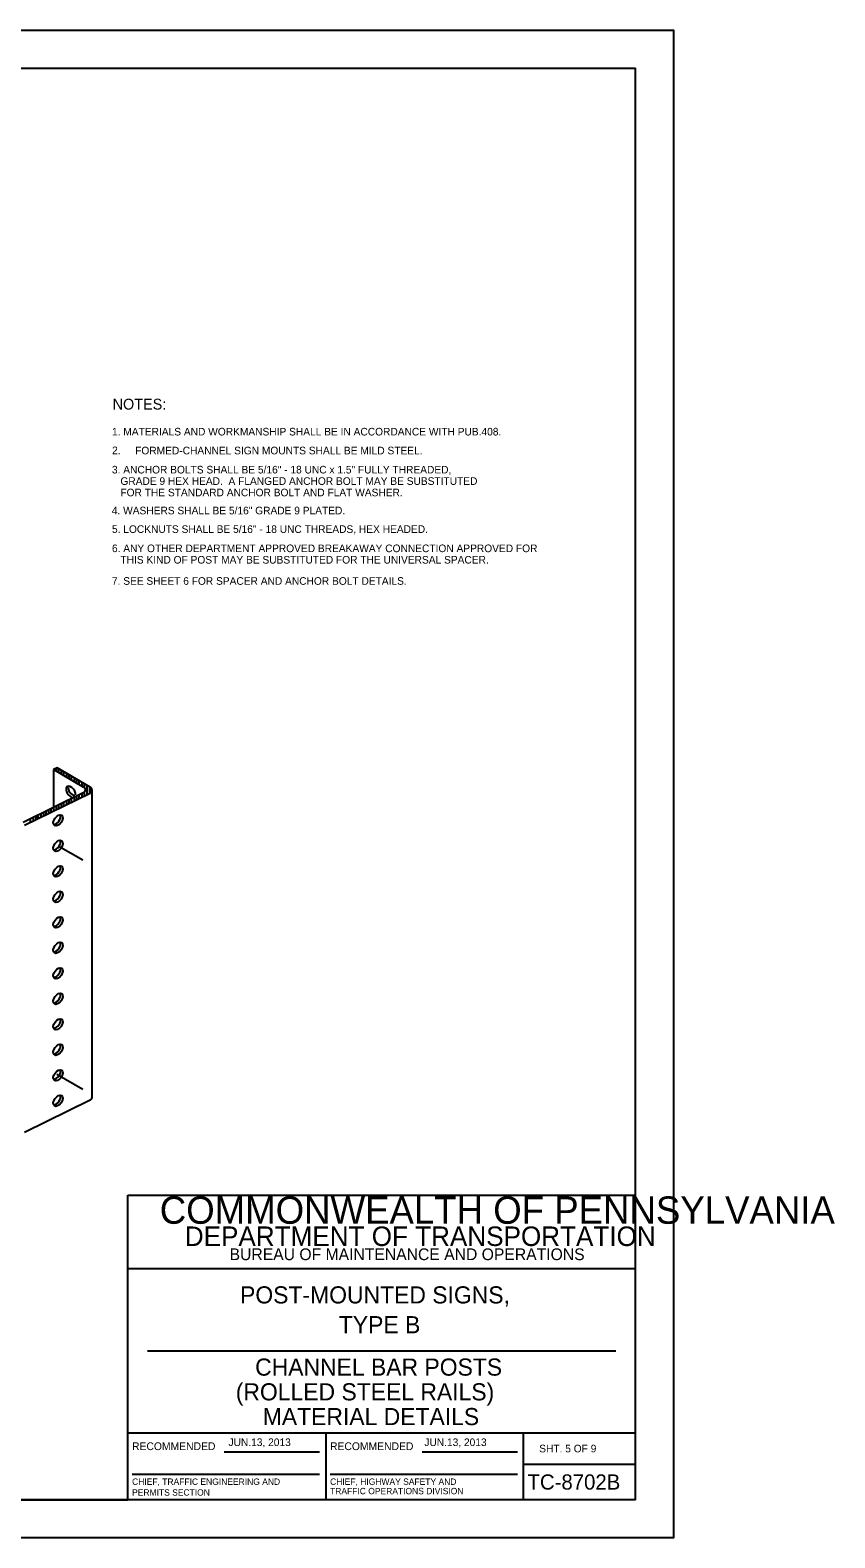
# Model space of a CAD drawing. Extents: x 644358 to 648627, y 294594 to 295782.
# Drawn here: x 648310 to 648627, y 295188 to 295782 of the extents above; entities that cross this region are included whole.
import ezdxf

# ---------------------------------------------------------------- set-up
doc = ezdxf.new("R2010")
doc.units = 0
for name, color, linetype in [('1', 7, 'Continuous'), ('2', 7, 'Continuous'), ('4', 7, 'Continuous'), ('PLT-BNDY', 7, 'Continuous')]:
    doc.layers.add(name, color=color, linetype=linetype)

msp = doc.modelspace()

# ---------------------------------------------------------------- linework, layer by layer
at = {"layer": '1'}
for p, q in [((647762.31, 295766.63), (648548.31, 295766.63)), ((648548.31, 295202.63), (648548.31, 295766.63)), ((648348.31, 295202.63), (648348.31, 295322.63)), ((648348.31, 295322.63), (648548.31, 295322.63)), ((648548.31, 295293.63), (648348.31, 295293.63)), ((648356.06, 295261.31), (648540.56, 295261.31)), ((648348.31, 295229), (648548.31, 295229)), ((648426.31, 295229), (648426.31, 295202.63)), ((648504.19, 295202.63), (648504.19, 295229)), ((648386.24, 295221.57), (648423.87, 295221.57)), ((648464.24, 295221.57), (648501.87, 295221.57)), ((648349.99, 295212.68), (648423.87, 295212.68)), ((648427.99, 295212.68), (648501.87, 295212.68)), ((648504.19, 295216.63), (648548.31, 295216.63)), ((648548.31, 295202.63), (647762.31, 295202.63)), ((647762.31, 295202.63), (648348.31, 295202.63))]:
    msp.add_line(p, q, dxfattribs=at)
at = {"layer": '2'}
for p, q in [((648320.53, 295491.03), (648319.03, 295490.28)), ((648331.03, 295483.28), (648319.03, 295490.28)), ((648319.03, 295490.28), (648319.03, 295475.53)), ((648320.03, 295490.78), (648320.03, 295489.78)), ((648333.53, 295483.4), (648320.53, 295491.03)), ((648321.03, 295490.65), (648321.03, 295489.03)), ((648322.03, 295490.03), (648322.03, 295488.4)), ((648323.03, 295489.53), (648323.03, 295487.9)), ((648324.15, 295488.9), (648324.15, 295487.28)), ((648325.03, 295488.4), (648325.03, 295486.78)), ((648326.03, 295487.78), (648326.03, 295486.15)), ((648327.15, 295487.15), (648327.15, 295485.53)), ((648328.15, 295486.53), (648328.15, 295485.03)), ((648329.03, 295485.9), (648329.03, 295484.4)), ((648330.15, 295485.4), (648330.15, 295483.9)), ((648307.03, 295469.65), (648331.03, 295481.4)), ((648307.65, 295468.4), (648333.53, 295481.03)), ((648327.15, 295479.4), (648327.15, 295477.9)), ((648327.4, 295479.53), (648327.4, 295479.53)), ((648328.15, 295479.9), (648328.15, 295478.4)), ((648329.03, 295480.53), (648329.03, 295479.03)), ((648330.15, 295480.9), (648330.15, 295479.4)), ((648331.15, 295484.78), (648331.15, 295483.15)), ((648331.15, 295481.53), (648331.15, 295479.9)), ((648332.15, 295484.15), (648332.15, 295480.4)), ((648333.15, 295483.65), (648333.15, 295480.9)), ((648334.15, 295482.4), (648334.15, 295360.9)), ((648315.03, 295473.53), (648315.03, 295472.03)), ((648316.03, 295474.03), (648316.03, 295472.53)), ((648317.03, 295474.53), (648317.03, 295473.03)), ((648318.03, 295474.9), (648318.03, 295473.53)), ((648319.03, 295475.53), (648319.03, 295474.03)), ((648320.03, 295476.03), (648320.03, 295474.53)), ((648321.03, 295476.4), (648321.03, 295474.9)), ((648322.03, 295477.03), (648322.03, 295475.53)), ((648323.03, 295477.53), (648323.03, 295476.03)), ((648324.15, 295477.9), (648324.15, 295476.4)), ((648325.03, 295478.4), (648325.03, 295476.9)), ((648326.03, 295479.03), (648326.03, 295477.53)), ((648309.9, 295471.03), (648309.9, 295469.53)), ((648311.03, 295471.53), (648311.03, 295470.15)), ((648312.03, 295472.03), (648312.03, 295470.53)), ((648312.9, 295472.53), (648312.9, 295471.03)), ((648314.03, 295473.03), (648314.03, 295471.53)), ((648319.4, 295468.28), (648319.4, 295468.28)), ((648319.4, 295458.28), (648319.4, 295458.28)), ((648330.53, 295454.65), (648320.9, 295460.15)), ((648319.4, 295448.15), (648319.4, 295448.15)), ((648319.4, 295438.15), (648319.4, 295438.15)), ((648319.4, 295428.15), (648319.4, 295428.15)), ((648319.4, 295418.03), (648319.4, 295418.03)), ((648319.4, 295408.03), (648319.4, 295408.03)), ((648319.4, 295398.03), (648319.4, 295398.03)), ((648319.4, 295387.9), (648319.4, 295387.9)), ((648319.4, 295377.9), (648319.4, 295377.9)), ((648319.4, 295367.9), (648319.4, 295367.9)), ((648330.53, 295364.28), (648320.28, 295370.15)), ((648307.65, 295347.4), (648333.53, 295360.15)), ((648319.4, 295357.9), (648319.4, 295357.9))]:
    msp.add_line(p, q, dxfattribs=at)
for centre, radius, start, end in [((648330.54, 295482.35), 1.08, 296.09542, 59.8656), ((648332.82, 295482.27), 1.35, 296.10629, 59.84607), ((648332.82, 295361.31), 1.35, 296.10629, 351.60882)]:
    msp.add_arc(centre, radius, start, end, dxfattribs=at)
for centre, major_axis, start_param, end_param in [((648325.85, 295481.54), (1.46, -2.03), 3.471768, 5.580344), ((648325.85, 295481.54), (1.46, -2.03), 0.572065, 3.471768), ((648326.72, 295482.16), (1.46, -2.03), 3.600978, 5.74606), ((648319.96, 295470.92), (-1.46, -2.03), 0.439655, 2.682207), ((648319.96, 295460.88), (-1.46, -2.03), 0.439655, 2.682207), ((648319.96, 295450.84), (-1.46, -2.03), 0.439655, 2.682207), ((648319.96, 295440.8), (-1.46, -2.03), 0.439655, 2.682207), ((648319.96, 295430.75), (-1.46, -2.03), 0.439655, 2.682207), ((648319.96, 295420.71), (-1.46, -2.03), 0.439655, 2.682207), ((648319.96, 295410.67), (-1.46, -2.03), 0.439655, 2.682207), ((648319.96, 295400.62), (-1.46, -2.03), 0.439655, 2.682207), ((648319.96, 295390.58), (-1.46, -2.03), 0.439655, 2.682207), ((648319.96, 295380.54), (-1.46, -2.03), 0.439655, 2.682207), ((648319.96, 295370.5), (-1.46, -2.03), 0.439655, 2.682207), ((648319.96, 295360.45), (-1.46, -2.03), 0.439655, 2.682207)]:
    msp.add_ellipse(centre, major_axis=major_axis, ratio=0.589639, start_param=start_param, end_param=end_param, dxfattribs=at)
for centre in [(648320.83, 295470.3), (648320.83, 295460.26), (648320.83, 295450.21), (648320.83, 295440.17), (648320.83, 295430.13), (648320.83, 295420.09), (648320.83, 295410.04), (648320.83, 295400), (648320.83, 295389.96), (648320.83, 295379.91), (648320.83, 295369.87), (648320.83, 295359.83)]:
    msp.add_ellipse(centre, major_axis=(-1.46, -2.03), ratio=0.589639, dxfattribs=at)
at = {"layer": 'PLT-BNDY'}
msp.add_lwpolyline([(647722.31, 295781.63), (648563.31, 295781.63), (648563.31, 295187.63), (647722.31, 295187.63)], close=True, dxfattribs=at)

# ---------------------------------------------------------------- texts
at = {"layer": '1'}
for s, height, p in [('COMMONWEALTH OF PENNSYLVANIA', 10.7828, (648360.9, 295311.36)), ('DEPARTMENT OF TRANSPORTATION', 7.6837, (648370.76, 295302.61)), ('BUREAU OF MAINTENANCE AND OPERATIONS', 4.6253, (648388.41, 295297.04)), ('POST-MOUNTED SIGNS,', 6.75, (648392.54, 295279.97)), ('TYPE B', 6.75, (648431.45, 295268.22)), ('CHANNEL BAR POSTS', 6.75, (648398.47, 295251.53)), ('(ROLLED STEEL RAILS)', 6.75, (648390.84, 295241.78)), ('MATERIAL DETAILS', 6.75, (648401.47, 295232.03)), ('RECOMMENDED', 3.048, (648349.99, 295222.2)), ('RECOMMENDED', 3.048, (648427.99, 295222.2)), ('SHT. 5 OF 9', 3, (648510.39, 295221.31)), ('TC-8702B', 6, (648505.77, 295206.63)), ('CHIEF, TRAFFIC ENGINEERING AND', 2.5, (648349.99, 295208.51)), ('PERMITS SECTION', 2.5, (648349.99, 295204.26)), ('TRAFFIC OPERATIONS DIVISION', 2.5, (648427.99, 295204.81)), ('CHIEF, HIGHWAY SAFETY AND', 2.5, (648427.99, 295208.51))]:
    msp.add_text(s, height=height, dxfattribs=at).set_placement(p)
at = {"layer": '2'}
for p in [(648387.98, 295223.79), (648465.14, 295223.79)]:
    msp.add_text('JUN.13, 2013', height=3, dxfattribs=at).set_placement(p)
at = {"layer": '4'}
for s, height, p in [('NOTES:', 4.25, (648342.32, 295632.15)), ('1. MATERIALS AND WORKMANSHIP SHALL BE IN ACCORDANCE WITH PUB.408.', 3, (648342.08, 295621.94)), ('2.', 3, (648342.12, 295614.57)), ('FORMED-CHANNEL SIGN MOUNTS SHALL BE MILD STEEL.', 3, (648351.2, 295614.5)), ('3. ANCHOR BOLTS SHALL BE 5/16" - 18 UNC x 1.5" FULLY THREADED,', 3, (648342.05, 295606.97)), ('   GRADE 9 HEX HEAD.  A FLANGED ANCHOR BOLT MAY BE SUBSTITUTED', 3, (648342.05, 295602.47)), ('   FOR THE STANDARD ANCHOR BOLT AND FLAT WASHER.', 3, (648342.05, 295597.97)), ('4. WASHERS SHALL BE 5/16" GRADE 9 PLATED.', 3, (648342, 295590.87)), ('5. LOCKNUTS SHALL BE 5/16" - 18 UNC THREADS, HEX HEADED.', 3, (648342.07, 295583.54)), ('6. ANY OTHER DEPARTMENT APPROVED BREAKAWAY CONNECTION APPROVED FOR', 3, (648342.06, 295575.97)), ('   THIS KIND OF POST MAY BE SUBSTITUTED FOR THE UNIVERSAL SPACER.', 3, (648342.06, 295571.47)), ('7. SEE SHEET 6 FOR SPACER AND ANCHOR BOLT DETAILS.', 3, (648342.05, 295563.11))]:
    msp.add_text(s, height=height, dxfattribs=at).set_placement(p)

doc.saveas('drawing.dxf')
